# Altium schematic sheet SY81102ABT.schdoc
size 127 x 101 mm
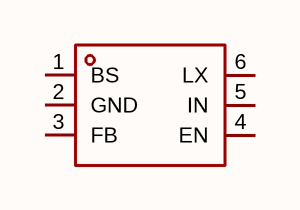
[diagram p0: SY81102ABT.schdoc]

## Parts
U?  sy81102abt  [SOT-23-6_L2.9-W1.6-P0.95-LS2.8-BL]  (value not drawn)

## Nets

Not connected (* = marked no-connect by the designer): U? 1(BS) 2(GND) 3(FB) 4(EN) 5(IN) 6(LX)

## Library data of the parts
U? = sy81102abt: 功能类型:降压型;工作电压:4.5V~18V;输出电压:600mV~9V;输出电流:2A;输出类型:可调;; Manufacturer: Silergy(矽力杰); AddInBom: yes; ModelId: 18da8f6c14a34920b3e136b5c401a119; ModelName: SOT-23-6_L2.9-W1.6-H1.5-LS2.8-P0.95; ModelTransform: 110.236,113.364,0,90,0,0,0.0005,0.0005,0; Function: 降压型; Output Current: 2A; Frequency - Switching: 500kHz; Synchronous Rectifier: 是; Number of Outputs: 1; Topology: 降压式; Quiescent Current: 200uA; Switch tube (built-in/external): 内置; Output Type: 可调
